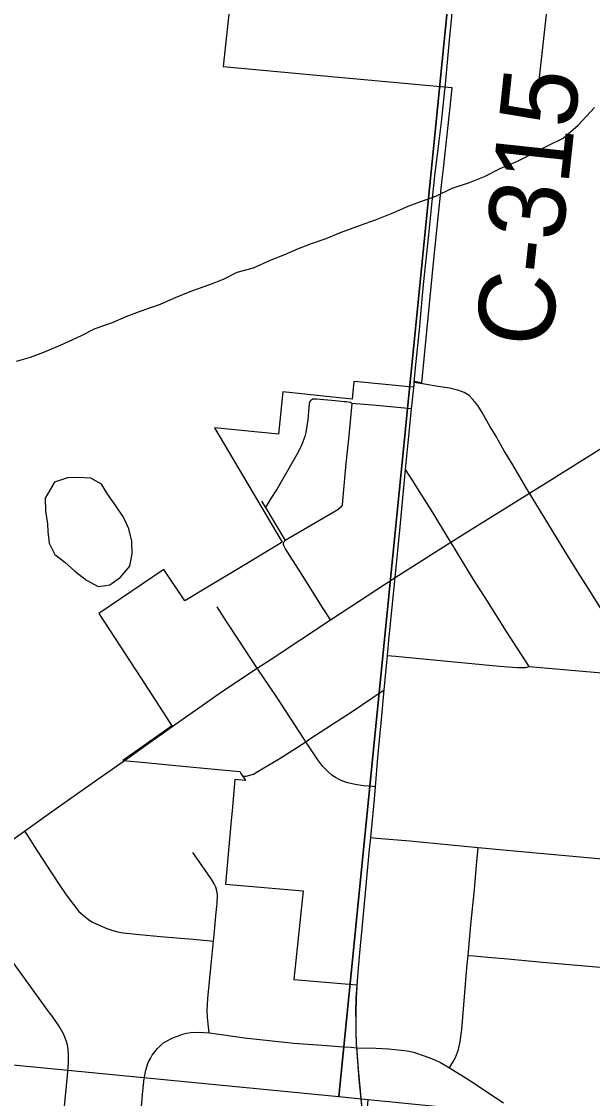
# Model space of a CAD drawing. Extents: x 831 to 1552, y 430 to 870.
# Drawn here: x 1316.8 to 1325.33, y 662.53 to 678.59 of the extents above; entities that cross this region are included whole.
import ezdxf

# ---------------------------------------------------------------- set-up
doc = ezdxf.new("R2010")
doc.units = 0
for name, color, linetype in [('GM_X_City_Street', 7, 'Continuous'), ('GM_X_Corporation', 7, 'Continuous'), ('GM_X_County_Road', 7, 'Continuous'), ('GM_X_County_Road_Text', 7, 'Continuous'), ('GM_X_Minor_Lake', 7, 'Continuous'), ('GM_X_Minor_River', 7, 'Continuous'), ('GM_X_Township_Road', 7, 'Continuous')]:
    doc.layers.add(name, color=color, linetype=linetype)

msp = doc.modelspace()

# ---------------------------------------------------------------- linework, layer by layer
at = {"layer": 'GM_X_City_Street'}
for p, q in [((1320.388, 671.435), (1320.446, 671.341)), ((1320.446, 671.341), (1320.741, 670.848))]:
    msp.add_line(p, q, dxfattribs=at)
for points in [[(1324.521, 677.569), (1324.535, 677.753), (1324.741, 679.595), (1324.753, 679.718), (1324.755, 679.769), (1324.75, 679.806), (1324.744, 679.837), (1324.732, 679.873), (1324.726, 679.888), (1324.714, 679.904), (1324.7, 679.917), (1324.685, 679.928), (1324.658, 679.943)], [(1324.386, 671.554), (1324.334, 671.642), (1324.137, 671.975), (1324.011, 672.185), (1323.921, 672.343), (1323.896, 672.391), (1323.801, 672.542), (1323.679, 672.758), (1323.614, 672.862), (1323.542, 672.952), (1323.485, 673.009), (1323.413, 673.056), (1323.334, 673.085), (1323.193, 673.117), (1323.024, 673.146), (1322.791, 673.185), (1322.667, 673.205)], [(1321.736, 672.891), (1321.718, 672.903), (1321.706, 672.907), (1321.651, 672.914), (1321.621, 672.917), (1321.488, 672.93), (1321.206, 672.957), (1321.18, 672.956), (1321.152, 672.953), (1321.136, 672.945), (1321.125, 672.937), (1321.115, 672.926), (1321.105, 672.908), (1321.099, 672.89), (1321.097, 672.868), (1321.094, 672.835), (1321.077, 672.648), (1321.047, 672.46), (1321.031, 672.398), (1320.987, 672.278), (1320.932, 672.163), (1320.618, 671.618), (1320.518, 671.458), (1320.446, 671.341)], [(1321.736, 672.891), (1321.687, 672.36), (1321.667, 672.177), (1321.647, 671.993), (1321.599, 671.5), (1321.589, 671.373)], [(1322.626, 672.809), (1322.572, 672.814), (1322.101, 672.858), (1321.736, 672.891)], [(1323.215, 670.822), (1323.165, 670.903), (1322.944, 671.263), (1322.686, 671.673), (1322.654, 671.724), (1322.537, 671.905)], [(1325.715, 669.411), (1325.323, 670.044), (1325.264, 670.137), (1325.113, 670.372), (1324.926, 670.671), (1324.538, 671.307), (1324.386, 671.554)], [(1321.589, 671.373), (1321.566, 671.34), (1321.526, 671.302), (1320.741, 670.848)], [(1321.417, 669.662), (1321.347, 669.772), (1321.299, 669.85), (1320.982, 670.352), (1320.816, 670.613), (1320.746, 670.723), (1320.73, 670.753), (1320.721, 670.773), (1320.717, 670.787), (1320.717, 670.809), (1320.723, 670.828), (1320.741, 670.848)], [(1324.383, 668.966), (1324.045, 669.491), (1323.75, 669.958), (1323.552, 670.266), (1323.215, 670.822)], [(1320.323, 668.944), (1320.039, 669.375), (1319.862, 669.64), (1319.726, 669.856)], [(1322.268, 669.134), (1322.387, 669.123), (1323.939, 668.975), (1324.132, 668.957), (1324.21, 668.951), (1324.278, 668.951), (1324.328, 668.955), (1324.383, 668.966)], [(1324.383, 668.966), (1326.038, 668.823), (1326.887, 668.75), (1327.724, 668.674), (1328.175, 668.631), (1329.422, 668.512)], [(1322.089, 667.171), (1322.046, 667.176), (1321.91, 667.19), (1321.785, 667.209), (1321.673, 667.233), (1321.602, 667.259), (1321.545, 667.284), (1321.49, 667.313), (1321.438, 667.348), (1321.39, 667.387), (1321.345, 667.43), (1321.304, 667.476), (1321.229, 667.576), (1321.047, 667.846), (1321.021, 667.885), (1320.613, 668.51), (1320.323, 668.944)], [(1320.104, 667.331), (1320.16, 667.333), (1320.213, 667.345), (1320.265, 667.363), (1320.397, 667.44), (1320.65, 667.591), (1320.87, 667.728), (1321.047, 667.846), (1321.109, 667.887), (1321.739, 668.297), (1322.047, 668.503), (1322.22, 668.619)], [(1322.018, 666.416), (1322.108, 666.408), (1322.601, 666.366), (1323.621, 666.27), (1324.268, 666.209), (1325.255, 666.12), (1325.819, 666.069), (1326.058, 666.048), (1326.861, 665.979), (1327.849, 665.892), (1327.92, 665.886), (1328.464, 665.832), (1328.781, 665.795), (1328.903, 665.781)], [(1323.193, 662.981), (1323.244, 663.068), (1323.283, 663.137), (1323.329, 663.254), (1323.353, 663.373), (1323.375, 663.555), (1323.421, 664.107), (1323.452, 664.475), (1323.471, 664.659), (1323.513, 665.115), (1323.565, 665.64), (1323.596, 666.004), (1323.611, 666.159), (1323.621, 666.27)], [(1323.471, 664.659), (1323.554, 664.654), (1323.763, 664.635), (1324.062, 664.606), (1324.58, 664.557), (1325.669, 664.464), (1325.995, 664.438), (1326.428, 664.396), (1326.8, 664.362), (1327.357, 664.311), (1327.771, 664.271), (1327.791, 664.27), (1328.284, 664.227), (1328.68, 664.191), (1328.966, 664.161)], [(1321.81, 663.283), (1322.095, 663.275), (1322.284, 663.264), (1322.47, 663.248), (1322.562, 663.234), (1322.656, 663.215), (1322.831, 663.157), (1322.948, 663.114), (1323.056, 663.06), (1323.193, 662.981), (1323.22, 662.966), (1323.483, 662.802), (1324.001, 662.46)]]:
    msp.add_lwpolyline(points, dxfattribs=at)
at = {"layer": 'GM_X_Corporation'}
for points in [[(1303.37, 684.858), (1323.531, 682.478), (1321.541, 662.548), (1301.887, 664.457), (1301.464, 664.502)], [(1323.531, 682.478), (1343.776, 680.603), (1341.746, 660.547), (1321.979, 662.503), (1321.541, 662.548)], [(1300.485, 650.938), (1320.907, 650.938), (1321.979, 662.503), (1321.541, 662.548), (1301.887, 664.457)]]:
    msp.add_lwpolyline(points, close=True, dxfattribs=at)
msp.add_lwpolyline([(1320.059, 680.176), (1319.814, 677.916), (1320.946, 677.812), (1321.157, 677.793), (1323.002, 677.623), (1323.228, 677.602), (1323.211, 677.449), (1323.097, 676.393), (1323.08, 676.235), (1323, 675.475), (1322.946, 674.936), (1322.87, 674.169), (1322.809, 673.558), (1322.773, 673.2), (1322.664, 673.217), (1322.656, 673.135), (1322.543, 673.146), (1321.826, 673.211), (1321.764, 673.217), (1321.741, 672.957), (1321.452, 672.987), (1320.705, 673.065), (1320.642, 672.435), (1319.683, 672.528), (1320.697, 670.822), (1320.616, 670.77), (1320.061, 670.438), (1319.578, 670.15), (1319.241, 669.948), (1318.928, 670.416), (1317.96, 669.756), (1318.583, 668.8), (1318.969, 668.206), (1319.05, 668.082), (1318.988, 668.039), (1318.316, 667.566), (1318.547, 667.544), (1319.365, 667.468), (1320.061, 667.404), (1320.09, 667.359), (1320.143, 667.28), (1320.15, 667.269), (1320.032, 667.279), (1319.99, 667.283), (1319.947, 666.813), (1319.934, 666.67), (1319.849, 665.724), (1321.007, 665.621), (1320.868, 664.302), (1321.697, 664.228), (1321.81, 664.218), (1321.803, 664.07), (1321.802, 664.066), (1321.802, 664.062), (1321.802, 664.059), (1321.802, 664.055), (1321.802, 664.051), (1321.802, 664.047), (1321.802, 664.044), (1321.801, 664.04), (1321.801, 664.036), (1321.801, 664.032), (1321.801, 664.029), (1321.801, 664.025), (1321.801, 664.021), (1321.801, 664.017), (1321.8, 664.014), (1321.8, 664.01), (1321.8, 664.006), (1321.8, 664.003), (1321.8, 663.999), (1321.8, 663.995), (1321.8, 663.994), (1321.8, 663.991), (1321.8, 663.988), (1321.799, 663.984), (1321.799, 663.98), (1321.799, 663.976), (1321.799, 663.973), (1321.799, 663.969), (1321.799, 663.965), (1321.799, 663.962), (1321.799, 663.958), (1321.799, 663.954), (1321.798, 663.95), (1321.798, 663.947), (1321.798, 663.943), (1321.798, 663.939), (1321.798, 663.935), (1321.798, 663.932), (1321.798, 663.928), (1321.798, 663.924), (1321.798, 663.92), (1321.798, 663.917), (1321.798, 663.913), (1321.797, 663.909), (1321.797, 663.906), (1321.797, 663.902), (1321.797, 663.898), (1321.797, 663.894), (1321.797, 663.891), (1321.797, 663.887), (1321.797, 663.883), (1321.797, 663.879), (1321.797, 663.876), (1321.797, 663.872), (1321.797, 663.868), (1321.797, 663.864), (1321.797, 663.861), (1321.796, 663.857), (1321.796, 663.853), (1321.796, 663.846), (1321.796, 663.842), (1321.793, 663.809), (1321.794, 663.701), (1321.795, 663.546), (1321.802, 663.332), (1321.805, 663.294), (1321.827, 662.96), (1321.868, 662.528), (1321.913, 662.095)], dxfattribs=at)
at = {"layer": 'GM_X_County_Road'}
for p, q in [((1322.663, 673.165), (1322.667, 673.205)), ((1322.381, 670.293), (1323.215, 670.822)), ((1321.417, 669.662), (1322.381, 670.293)), ((1322.22, 668.619), (1322.268, 669.134)), ((1315.814, 665.779), (1316.848, 666.513))]:
    msp.add_line(p, q, dxfattribs=at)
for points in [[(1323.124, 677.561), (1323.129, 677.6), (1323.199, 678.366), (1323.217, 678.557), (1323.25, 678.873), (1323.275, 679.118), (1323.317, 679.53)], [(1323.039, 676.806), (1323.072, 677.085), (1323.124, 677.561)], [(1322.765, 674.22), (1322.807, 674.664), (1322.882, 675.408), (1322.932, 675.904), (1322.976, 676.287), (1323.039, 676.806)], [(1322.667, 673.205), (1322.686, 673.42), (1322.748, 674.038), (1322.765, 674.22)], [(1322.626, 672.809), (1322.658, 673.124), (1322.663, 673.165)], [(1322.537, 671.905), (1322.59, 672.454), (1322.626, 672.809)], [(1324.386, 671.554), (1324.634, 671.708), (1325.557, 672.285)], [(1322.381, 670.293), (1322.454, 671.049), (1322.537, 671.905)], [(1323.215, 670.822), (1323.385, 670.93), (1324.386, 671.554)], [(1322.268, 669.134), (1322.294, 669.41), (1322.381, 670.293)], [(1320.323, 668.944), (1320.529, 669.079), (1321.417, 669.662)], [(1319.705, 668.529), (1319.832, 668.618), (1320.323, 668.944)], [(1318.827, 667.912), (1318.909, 667.971), (1319.052, 668.071), (1319.5, 668.386), (1319.705, 668.529)], [(1322.089, 667.171), (1322.125, 667.611), (1322.184, 668.234), (1322.22, 668.619)], [(1317.993, 667.321), (1318.32, 667.55), (1318.827, 667.912)], [(1316.848, 666.513), (1317.356, 666.873), (1317.993, 667.321)], [(1322.018, 666.416), (1322.074, 666.989), (1322.089, 667.171)], [(1321.81, 663.283), (1321.807, 663.321), (1321.8, 663.536), (1321.798, 663.691), (1321.797, 663.798), (1321.802, 664.032), (1321.813, 664.204), (1321.824, 664.35), (1321.854, 664.696), (1321.909, 665.268), (1322.001, 666.245), (1322.018, 666.416)], [(1321.839, 662.867), (1321.832, 662.95), (1321.81, 663.283)], [(1321.621, 657.358), (1321.637, 657.558), (1321.694, 658.239), (1321.756, 658.92), (1321.803, 659.478), (1321.832, 659.85), (1321.893, 660.531), (1321.949, 661.213), (1321.951, 661.525), (1321.947, 661.712), (1321.917, 662.084), (1321.872, 662.517), (1321.839, 662.867)]]:
    msp.add_lwpolyline(points, dxfattribs=at)
at = {"layer": 'GM_X_Minor_Lake'}
for points in [[(1317.297, 671.717), (1317.157, 671.476), (1317.163, 671.286), (1317.191, 671.096), (1317.197, 670.982), (1317.217, 670.807), (1317.299, 670.639), (1317.449, 670.523), (1317.6, 670.392), (1317.773, 670.253), (1317.946, 670.16), (1318.057, 670.178)], [(1318.057, 670.178), (1318.122, 670.188), (1318.282, 670.3), (1318.421, 670.465), (1318.454, 670.647), (1318.449, 670.837), (1318.405, 671.02), (1318.324, 671.196), (1318.212, 671.364), (1318.093, 671.532), (1317.996, 671.686), (1317.837, 671.779), (1317.64, 671.789), (1317.488, 671.783), (1317.297, 671.717)]]:
    msp.add_lwpolyline(points, dxfattribs=at)
at = {"layer": 'GM_X_Minor_River'}
msp.add_lwpolyline([(1316.727, 673.524), (1316.94, 673.582), (1317.139, 673.655), (1317.398, 673.766), (1317.689, 673.899), (1317.903, 674.01), (1318.162, 674.098), (1318.368, 674.187), (1318.605, 674.275), (1318.88, 674.37), (1319.078, 674.459), (1319.346, 674.569), (1319.613, 674.665), (1319.819, 674.746), (1320.025, 674.85), (1320.269, 674.915), (1320.529, 675.033), (1320.735, 675.114), (1320.941, 675.203), (1321.132, 675.276), (1321.353, 675.349), (1321.567, 675.438), (1321.865, 675.548), (1322.086, 675.629), (1322.361, 675.739), (1322.575, 675.835), (1322.766, 675.901), (1322.987, 675.982), (1323.232, 676.101), (1323.491, 676.188), (1323.713, 676.277), (1323.95, 676.395), (1324.209, 676.506), (1324.408, 676.602), (1324.645, 676.728), (1324.89, 676.847), (1325.112, 677.042), (1325.359, 677.304)], dxfattribs=at)
at = {"layer": 'GM_X_Township_Road'}
for points in [[(1316.848, 666.513), (1316.891, 666.446), (1316.995, 666.289), (1317.166, 666.021), (1317.365, 665.716), (1317.471, 665.563), (1317.581, 665.416), (1317.662, 665.315), (1317.754, 665.233), (1317.802, 665.197), (1317.856, 665.162), (1317.963, 665.11), (1318.08, 665.062), (1318.15, 665.036), (1318.239, 665.013), (1318.32, 664.998), (1318.566, 664.97), (1318.879, 664.939), (1319.367, 664.899), (1319.625, 664.876), (1319.67, 664.872)], [(1319.67, 664.872), (1319.689, 665.068), (1319.706, 665.253), (1319.724, 665.432), (1319.73, 665.555), (1319.722, 665.62), (1319.704, 665.675), (1319.679, 665.728), (1319.647, 665.786), (1319.581, 665.879), (1319.359, 666.195)], [(1317.442, 662.355), (1317.489, 662.868), (1317.504, 663.056), (1317.504, 663.184), (1317.499, 663.258), (1317.491, 663.325), (1317.477, 663.373), (1317.453, 663.439), (1317.43, 663.49), (1317.369, 663.594), (1317.265, 663.746), (1317.224, 663.802), (1316.719, 664.499), (1316.35, 665.024), (1316.136, 665.321), (1315.856, 665.719), (1315.814, 665.779)], [(1319.604, 663.504), (1319.599, 663.55), (1319.579, 663.734), (1319.576, 663.837), (1319.579, 663.929), (1319.586, 664.017), (1319.635, 664.521), (1319.67, 664.872)], [(1318.925, 663.353), (1318.977, 663.387), (1319.032, 663.416), (1319.089, 663.441), (1319.147, 663.462), (1319.205, 663.484), (1319.269, 663.501), (1319.333, 663.509), (1319.458, 663.514), (1319.604, 663.504)], [(1319.604, 663.504), (1319.647, 663.501), (1320.132, 663.432), (1320.868, 663.35), (1321.362, 663.313), (1321.541, 663.302), (1321.725, 663.289), (1321.81, 663.283)], [(1318.584, 662.252), (1318.587, 662.291), (1318.617, 662.634), (1318.636, 662.822), (1318.661, 662.95), (1318.697, 663.06), (1318.727, 663.124), (1318.755, 663.17), (1318.793, 663.22), (1318.834, 663.269), (1318.878, 663.313), (1318.925, 663.353)]]:
    msp.add_lwpolyline(points, dxfattribs=at)

# ---------------------------------------------------------------- texts
at = {"layer": 'GM_X_County_Road_Text'}
msp.add_text('C-315', height=1.1364, rotation=83.8748, dxfattribs=at).set_placement((1324.704, 673.701))

doc.saveas('drawing.dxf')
